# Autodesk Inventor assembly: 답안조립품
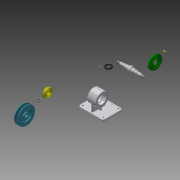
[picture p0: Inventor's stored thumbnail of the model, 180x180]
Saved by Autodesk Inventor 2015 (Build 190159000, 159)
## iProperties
Created: 2019-09
Part Number: 답안조립품
Document SubType Name: Assembly
Designer: now
Author: now
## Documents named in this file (10)
- C:\Users\now\Desktop\490904V1036\답안조립품.iam
- C:\Users\now\Desktop\490904V1036\V-벨트풀리.ipt
- C:\Users\now\Desktop\490904V1036\너트 M10x1.ipt
- C:\Users\now\Desktop\490904V1036\베어링 6004.ipt
- C:\Users\now\Desktop\490904V1036\본체.ipt
- C:\Users\now\Desktop\490904V1036\볼트 M4.ipt
- C:\Users\now\Desktop\490904V1036\오일 실 17 30 5.ipt
- C:\Users\now\Desktop\490904V1036\축.ipt
- C:\Users\now\Desktop\490904V1036\커버.ipt
- C:\Users\now\Desktop\490904V1036\키 5 x 5 x 12.ipt
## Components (1 placed, 1 different names)
1. V-벨트풀리:1
